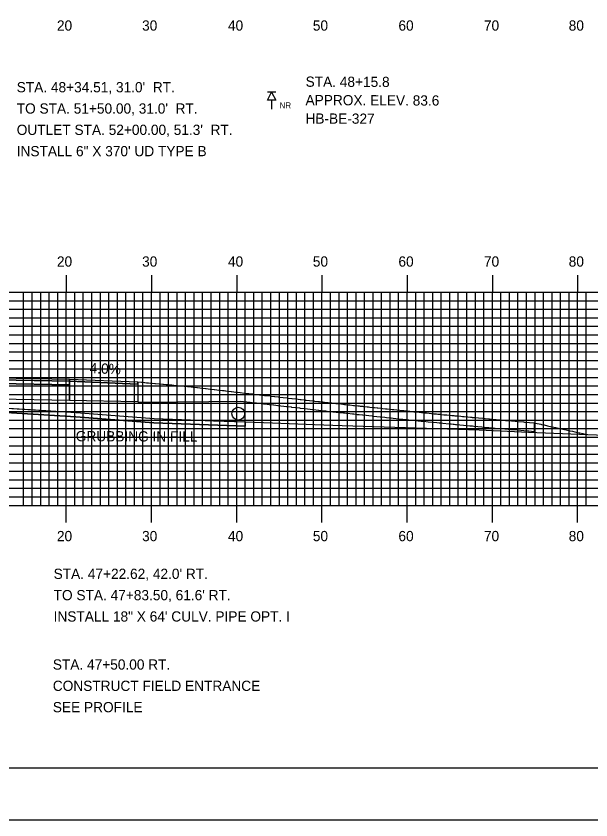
# Model space of a CAD drawing. Extents: x 1754708 to 1755051, y 442591 to 442811.
# Drawn here: x 1754887.6 to 1754955.1, y 442590.5 to 442684.8 of the extents above; entities that cross this region are included whole.
import ezdxf

# ---------------------------------------------------------------- set-up
doc = ezdxf.new("R2010")
doc.units = 0
for name, color, linetype in [('ANNOTATION', 7, 'Continuous'), ('BORDER', 7, 'Continuous'), ('BORING - NO REFUSAL', 7, 'Continuous'), ('D_Drainage_Culvert', 7, 'Continuous'), ('D_Roadway_Centerline', 7, 'Continuous'), ('D_Roadway_Drive_Gravel_RT', 7, 'Continuous'), ('D_Roadway_Drive_SubGrade', 7, 'Continuous'), ('D_Roadway_Edge_Shoulder', 7, 'Continuous'), ('D_Roadway_Edge_TW', 7, 'Continuous'), ('D_Roadway_Pavement', 7, 'Continuous'), ('D_Roadway_SubGrade', 7, 'Continuous'), ('D_Text_Standard', 7, 'Continuous'), ('DIMENSIONS', 7, 'Continuous'), ('GRUBBING IN FILL', 7, 'Continuous'), ('H_V ANNOTATION', 7, 'Continuous'), ('MAJOR', 7, 'Continuous'), ('MINOR', 7, 'Continuous'), ('PLOT BOUNDARY', 7, 'Continuous'), ('S_Roadway_Centerline', 7, 'Continuous')]:
    doc.layers.add(name, color=color, linetype=linetype)

msp = doc.modelspace()

# ---------------------------------------------------------------- linework, layer by layer
at = {"layer": 'ANNOTATION'}
msp.add_lwpolyline([(1754901.917, 442641.915), (1754908.167, 442641.346), (1754913.52, 442640.719)], dxfattribs=at)
at = {"layer": 'BORDER'}
msp.add_lwpolyline([(1754723.917, 442596.665), (1755043.917, 442596.665), (1755043.917, 442806.665), (1754723.917, 442806.665)], close=True, dxfattribs=at)
at = {"layer": 'BORING - NO REFUSAL'}
for p, q in [((1754918.097, 442675.912), (1754917.138, 442675.912)), ((1754917.617, 442674.952), (1754917.617, 442673.893))]:
    msp.add_line(p, q, dxfattribs=at)
msp.add_lwpolyline([(1754917.617, 442675.912), (1754918.097, 442674.952), (1754917.138, 442674.952)], close=True, dxfattribs=at)
at = {"layer": 'D_Drainage_Culvert'}
msp.add_circle((1754913.694, 442638.189), 0.75, dxfattribs=at)
at = {"layer": 'D_Roadway_Centerline'}
for points in [[(1754839.343, 442638.54), (1754843.343, 442639.54), (1754853.517, 442642.083), (1754861.517, 442642.403), (1754873.517, 442642.643), (1754885.517, 442642.403), (1754893.917, 442642.235), (1754901.917, 442641.915)], [(1754901.917, 442641.915), (1754902.417, 442641.87), (1754902.917, 442641.825), (1754903.417, 442641.78), (1754903.917, 442641.735), (1754904.417, 442641.69), (1754904.917, 442641.645), (1754905.417, 442641.6), (1754905.917, 442641.555), (1754906.417, 442641.51), (1754906.917, 442641.465), (1754907.417, 442641.42), (1754907.917, 442641.375), (1754907.917, 442641.375), (1754908.417, 442641.316), (1754908.917, 442641.258), (1754909.417, 442641.199), (1754909.917, 442641.141), (1754910.417, 442641.082), (1754910.472, 442641.076), (1754910.917, 442641.024), (1754910.917, 442641.024), (1754911.417, 442640.965), (1754911.417, 442640.965), (1754911.917, 442640.907), (1754911.917, 442640.907), (1754912.045, 442640.892), (1754912.046, 442640.892), (1754912.417, 442640.848), (1754912.419, 442640.848), (1754912.918, 442640.79), (1754912.921, 442640.789), (1754913.419, 442640.731), (1754913.421, 442640.731), (1754913.62, 442640.708), (1754913.623, 442640.707), (1754913.92, 442640.673), (1754913.926, 442640.672), (1754914.422, 442640.614), (1754914.429, 442640.614), (1754914.925, 442640.556), (1754915.194, 442640.524), (1754915.2, 442640.524), (1754915.423, 442640.498), (1754915.428, 442640.497), (1754915.439, 442640.496), (1754915.932, 442640.439), (1754915.945, 442640.437), (1754916.436, 442640.38), (1754916.773, 442640.341), (1754916.785, 442640.34), (1754916.936, 442640.322), (1754916.942, 442640.322), (1754916.96, 442640.32), (1754917.448, 442640.263), (1754917.47, 442640.261), (1754917.955, 442640.205), (1754917.976, 442640.203), (1754918.38, 442640.156), (1754918.459, 442640.147), (1754918.463, 442640.146), (1754918.492, 442640.143), (1754918.973, 442640.088), (1754919.447, 442640.033), (1754919.483, 442640.029), (1754919.52, 442640.026), (1754919.986, 442639.972), (1754919.995, 442639.971), (1754919.995, 442639.971), (1754920.037, 442639.967), (1754920.509, 442639.912), (1754920.974, 442639.858), (1754921.023, 442639.854), (1754921.074, 442639.849), (1754921.54, 442639.795), (1754921.598, 442639.788), (1754921.605, 442639.788), (1754921.654, 442639.783), (1754922.057, 442639.737), (1754922.511, 442639.684), (1754922.577, 442639.678), (1754922.644, 442639.672), (1754923.098, 442639.62), (1754923.22, 442639.606), (1754923.24, 442639.604), (1754923.565, 442639.567), (1754923.621, 442639.561), (1754924.062, 442639.511), (1754924.146, 442639.503), (1754924.232, 442639.494), (1754924.673, 442639.444), (1754924.854, 442639.423), (1754924.893, 442639.42), (1754925.145, 442639.391), (1754925.202, 442639.386), (1754925.302, 442639.376), (1754925.734, 442639.327), (1754926.155, 442639.279), (1754926.267, 442639.269), (1754926.502, 442639.242), (1754926.567, 442639.236), (1754926.62, 442639.231), (1754926.803, 442639.21), (1754927.213, 442639.164), (1754927.341, 442639.151), (1754927.745, 442639.106), (1754927.882, 442639.093), (1754927.981, 442639.084), (1754928.265, 442639.052), (1754928.382, 442639.039), (1754928.425, 442639.034), (1754928.817, 442638.991), (1754928.971, 442638.976), (1754929.131, 442638.961), (1754929.52, 442638.917), (1754929.664, 442638.904), (1754929.99, 442638.868), (1754930.046, 442638.861), (1754930.072, 442638.859), (1754930.444, 442638.818), (1754930.627, 442638.8), (1754930.991, 442638.76), (1754931.185, 442638.742), (1754931.54, 442638.703), (1754931.744, 442638.684), (1754931.745, 442638.684), (1754931.746, 442638.683), (1754931.959, 442638.664), (1754932.311, 442638.625), (1754932.651, 442638.588), (1754932.879, 442638.566), (1754933.116, 442638.544), (1754933.45, 442638.508), (1754933.497, 442638.503), (1754933.531, 442638.5), (1754933.808, 442638.469), (1754934.026, 442638.449), (1754934.289, 442638.425), (1754934.605, 442638.391), (1754934.909, 442638.358), (1754935.187, 442638.332), (1754935.273, 442638.323), (1754935.355, 442638.316), (1754935.564, 442638.293), (1754935.774, 442638.274), (1754936.08, 442638.246), (1754936.365, 442638.215), (1754936.64, 442638.186), (1754936.961, 442638.157), (1754937.104, 442638.144), (1754937.218, 442638.132), (1754937.367, 442638.116), (1754937.56, 442638.098), (1754937.813, 442638.071), (1754938.164, 442638.04), (1754938.534, 442638.007), (1754938.773, 442637.981), (1754938.994, 442637.962), (1754939.126, 442637.948), (1754939.292, 442637.933), (1754939.387, 442637.923), (1754939.792, 442637.887), (1754940.006, 442637.864), (1754940.21, 442637.843), (1754940.629, 442637.806), (1754940.946, 442637.778), (1754941.082, 442637.764), (1754941.134, 442637.758), (1754941.258, 442637.747), (1754941.436, 442637.729), (1754941.893, 442637.689), (1754942.376, 442637.646), (1754942.533, 442637.63), (1754942.662, 442637.617), (1754943.091, 442637.58), (1754943.16, 442637.574), (1754943.178, 442637.572), (1754943.704, 442637.526), (1754943.83, 442637.513), (1754943.949, 442637.501), (1754944.487, 442637.455), (1754945.06, 442637.406), (1754945.151, 442637.396), (1754945.152, 442637.396), (1754945.158, 442637.396), (1754945.748, 442637.345), (1754945.821, 442637.338), (1754945.891, 442637.331), (1754946.498, 442637.279), (1754946.551, 442637.274), (1754947.182, 442637.221), (1754947.284, 442637.212), (1754947.289, 442637.212), (1754947.859, 442637.164), (1754947.873, 442637.162), (1754948.432, 442637.115), (1754948.571, 442637.085), (1754949.199, 442636.948), (1754949.276, 442636.932), (1754949.459, 442636.892), (1754949.49, 442636.885), (1754949.57, 442636.868), (1754949.989, 442636.776), (1754950.498, 442636.663), (1754950.71, 442636.617), (1754950.971, 442636.56), (1754951.439, 442636.457), (1754951.618, 442636.417), (1754951.766, 442636.384), (1754951.972, 442636.339), (1754952.176, 442636.294), (1754952.618, 442636.196), (1754952.922, 442636.128), (1754953.168, 442636.072), (1754953.677, 442635.96), (1754953.784, 442635.936), (1754954.127, 442635.859), (1754954.392, 442635.8), (1754954.441, 442635.789), (1754954.542, 442635.766), (1754954.631, 442635.746)]]:
    msp.add_lwpolyline(points, dxfattribs=at)
at = {"layer": 'D_Roadway_Drive_Gravel_RT'}
msp.add_line((1754901.917, 442641.915), (1754901.917, 442639.575), dxfattribs=at)
at = {"layer": 'D_Roadway_Drive_SubGrade'}
for p, q in [((1754901.917, 442639.575), (1754902.917, 442639.555)), ((1754902.917, 442639.555), (1754913.917, 442639.666)), ((1754948.432, 442637.115), (1754948.432, 442636.112))]:
    msp.add_line(p, q, dxfattribs=at)
msp.add_lwpolyline([(1754913.917, 442639.666), (1754914.315, 442639.62), (1754914.322, 442639.619), (1754915.087, 442639.53), (1754915.093, 442639.529), (1754915.316, 442639.503), (1754915.332, 442639.502), (1754915.825, 442639.444), (1754915.838, 442639.443), (1754916.666, 442639.347), (1754916.679, 442639.345), (1754916.829, 442639.328), (1754916.854, 442639.325), (1754917.341, 442639.269), (1754917.363, 442639.267), (1754917.849, 442639.21), (1754917.87, 442639.208), (1754918.352, 442639.152), (1754918.386, 442639.149), (1754919.341, 442639.038), (1754919.414, 442639.031), (1754919.889, 442638.976), (1754919.931, 442638.972), (1754920.868, 442638.864), (1754920.969, 442638.854), (1754921.492, 442638.794), (1754921.549, 442638.788), (1754922.406, 442638.69), (1754922.539, 442638.677), (1754923.115, 442638.611), (1754923.135, 442638.609), (1754923.46, 442638.572), (1754923.516, 442638.567), (1754923.958, 442638.516), (1754924.128, 442638.5), (1754924.75, 442638.429), (1754924.789, 442638.425), (1754925.041, 442638.396), (1754925.198, 442638.381), (1754926.051, 442638.285), (1754926.163, 442638.274), (1754926.398, 442638.247), (1754926.516, 442638.236), (1754927.11, 442638.169), (1754927.238, 442638.157), (1754927.642, 442638.111), (1754927.878, 442638.089), (1754928.279, 442638.044), (1754928.322, 442638.04), (1754928.714, 442637.996), (1754929.029, 442637.966), (1754929.418, 442637.923), (1754929.562, 442637.909), (1754929.944, 442637.867), (1754929.97, 442637.864), (1754930.342, 442637.823), (1754930.525, 442637.806), (1754930.889, 442637.765), (1754931.084, 442637.747), (1754931.439, 442637.708), (1754931.644, 442637.689), (1754931.645, 442637.689), (1754931.858, 442637.669), (1754932.55, 442637.593), (1754933.016, 442637.549), (1754933.396, 442637.508), (1754933.431, 442637.505), (1754933.708, 442637.474), (1754934.189, 442637.43), (1754934.809, 442637.363), (1754935.088, 442637.337), (1754935.174, 442637.328), (1754935.256, 442637.321), (1754935.465, 442637.298), (1754935.981, 442637.251), (1754936.541, 442637.191), (1754937.005, 442637.149), (1754937.269, 442637.121), (1754937.462, 442637.103), (1754937.715, 442637.076), (1754938.437, 442637.011), (1754938.676, 442636.986), (1754938.897, 442636.966), (1754939.029, 442636.952), (1754939.195, 442636.937), (1754939.29, 442636.927), (1754939.695, 442636.891), (1754940.114, 442636.847), (1754940.85, 442636.782), (1754941.038, 442636.763), (1754941.163, 442636.752), (1754941.341, 442636.733), (1754942.281, 442636.651), (1754942.568, 442636.621), (1754943.065, 442636.578), (1754943.084, 442636.576), (1754943.61, 442636.53), (1754943.855, 442636.505), (1754944.966, 442636.41), (1754945.059, 442636.4), (1754945.656, 442636.349), (1754945.799, 442636.335), (1754946.406, 442636.283), (1754946.459, 442636.278), (1754947.192, 442636.216), (1754947.198, 442636.216), (1754947.768, 442636.168), (1754947.781, 442636.166), (1754948.432, 442636.112)], dxfattribs=at)
at = {"layer": 'D_Roadway_Edge_Shoulder'}
msp.add_lwpolyline([(1754893.917, 442642.235), (1754901.917, 442641.915), (1754901.917, 442641.665), (1754893.917, 442641.985)], close=True, dxfattribs=at)
at = {"layer": 'D_Roadway_Edge_TW'}
msp.add_lwpolyline([(1754885.517, 442642.403), (1754893.917, 442642.235), (1754893.917, 442641.985), (1754885.517, 442642.153)], close=True, dxfattribs=at)
at = {"layer": 'D_Roadway_Pavement'}
msp.add_lwpolyline([(1754885.517, 442642.153), (1754893.917, 442641.985), (1754893.917, 442641.568), (1754885.517, 442641.736)], close=True, dxfattribs=at)
msp.add_lwpolyline([(1754893.917, 442641.985), (1754893.917, 442641.568)], dxfattribs=at)
msp.add_lwpolyline([(1754893.917, 442641.985), (1754893.917, 442641.568)], dxfattribs=at)
msp.add_lwpolyline([(1754893.917, 442641.985), (1754893.917, 442641.568)], dxfattribs=at)
at = {"layer": 'D_Roadway_SubGrade'}
for points in [[(1754885.517, 442641.736), (1754893.917, 442641.568), (1754893.917, 442639.735), (1754885.517, 442639.903)], [(1754893.917, 442641.568), (1754893.917, 442641.985), (1754901.917, 442641.665), (1754901.917, 442641.915), (1754901.917, 442639.575), (1754893.917, 442639.735)]]:
    msp.add_lwpolyline(points, close=True, dxfattribs=at)
at = {"layer": 'DIMENSIONS'}
msp.add_line((1754901.917, 442641.915), (1754901.917, 442641.915), dxfattribs=at)
at = {"layer": 'GRUBBING IN FILL'}
msp.add_line((1754914.492, 442637.226), (1754914.492, 442636.725), dxfattribs=at)
msp.add_line((1754914.492, 442637.226), (1754914.492, 442636.725), dxfattribs=at)
msp.add_lwpolyline([(1754843.956, 442639.552), (1754848.929, 442638.411), (1754850.713, 442637.977), (1754852.447, 442637.469), (1754852.823, 442637.507), (1754860.439, 442638.236), (1754865.065, 442638.592), (1754876.12, 442638.705), (1754883.943, 442638.499), (1754894.644, 442637.829), (1754903.808, 442637.109), (1754914.492, 442636.725)], dxfattribs=at)
msp.add_lwpolyline([(1754843.956, 442639.552), (1754848.929, 442638.411), (1754850.713, 442637.977), (1754852.447, 442637.469), (1754852.823, 442637.507), (1754860.439, 442638.236), (1754865.065, 442638.592), (1754876.12, 442638.705), (1754883.943, 442638.499), (1754894.644, 442637.829), (1754903.808, 442637.109), (1754914.492, 442636.725)], dxfattribs=at)
msp.add_lwpolyline([(1754873.517, 442639.179), (1754876.124, 442639.205), (1754880.045, 442639.102), (1754883.966, 442638.999), (1754889.322, 442638.663), (1754894.679, 442638.328), (1754899.258, 442637.968), (1754903.837, 442637.608), (1754910.777, 442637.359), (1754914.492, 442637.226), (1754914.492, 442636.725), (1754909.15, 442636.917), (1754903.808, 442637.109), (1754899.226, 442637.469), (1754894.644, 442637.829), (1754883.943, 442638.499), (1754880.032, 442638.602), (1754876.12, 442638.705), (1754873.517, 442638.679)], close=True, dxfattribs=at)
msp.add_lwpolyline([(1754873.517, 442639.179), (1754876.124, 442639.205), (1754880.045, 442639.102), (1754883.966, 442638.999), (1754889.322, 442638.663), (1754894.679, 442638.328), (1754899.258, 442637.968), (1754903.837, 442637.608), (1754910.777, 442637.359), (1754914.492, 442637.226), (1754914.492, 442636.725), (1754909.15, 442636.917), (1754903.808, 442637.109), (1754899.226, 442637.469), (1754894.644, 442637.829), (1754883.943, 442638.499), (1754880.032, 442638.602), (1754876.12, 442638.705), (1754873.517, 442638.679)], close=True, dxfattribs=at)
at = {"layer": 'MAJOR'}
for p, q in [((1754893.517, 442654.44), (1754893.517, 442652.436)), ((1754903.517, 442654.44), (1754903.517, 442652.436)), ((1754913.517, 442654.44), (1754913.517, 442652.436)), ((1754923.517, 442654.44), (1754923.517, 442652.436)), ((1754933.517, 442654.44), (1754933.517, 442652.436)), ((1754943.517, 442654.44), (1754943.517, 442652.436)), ((1754953.517, 442654.44), (1754953.517, 442652.436)), ((1754733.517, 442652.436), (1755013.517, 442652.436)), ((1754733.517, 442652.436), (1755013.517, 442652.436)), ((1754893.517, 442627.436), (1754893.517, 442652.436)), ((1754903.517, 442627.436), (1754903.517, 442652.436)), ((1754913.517, 442627.436), (1754913.517, 442652.436)), ((1754923.517, 442627.436), (1754923.517, 442652.436)), ((1754933.517, 442627.436), (1754933.517, 442652.436)), ((1754943.517, 442627.436), (1754943.517, 442652.436)), ((1754953.517, 442627.436), (1754953.517, 442652.436)), ((1754733.517, 442647.436), (1755013.517, 442647.436)), ((1754733.517, 442642.436), (1755013.517, 442642.436)), ((1754733.517, 442637.436), (1755013.517, 442637.436)), ((1754733.517, 442632.436), (1755013.517, 442632.436)), ((1754733.517, 442627.436), (1755013.517, 442627.436)), ((1754733.517, 442627.436), (1755013.517, 442627.436)), ((1754893.517, 442625.432), (1754893.517, 442627.436)), ((1754903.517, 442625.432), (1754903.517, 442627.436)), ((1754913.517, 442625.432), (1754913.517, 442627.436)), ((1754923.517, 442625.432), (1754923.517, 442627.436)), ((1754933.517, 442625.432), (1754933.517, 442627.436)), ((1754943.517, 442625.432), (1754943.517, 442627.436)), ((1754953.517, 442625.432), (1754953.517, 442627.436))]:
    msp.add_line(p, q, dxfattribs=at)
at = {"layer": 'MINOR'}
for p, q in [((1754888.517, 442627.436), (1754888.517, 442652.436)), ((1754889.517, 442627.436), (1754889.517, 442652.436)), ((1754890.517, 442627.436), (1754890.517, 442652.436)), ((1754891.517, 442627.436), (1754891.517, 442652.436)), ((1754892.517, 442627.436), (1754892.517, 442652.436)), ((1754894.517, 442627.436), (1754894.517, 442652.436)), ((1754895.517, 442627.436), (1754895.517, 442652.436)), ((1754896.517, 442627.436), (1754896.517, 442652.436)), ((1754897.517, 442627.436), (1754897.517, 442652.436)), ((1754898.517, 442627.436), (1754898.517, 442652.436)), ((1754899.517, 442627.436), (1754899.517, 442652.436)), ((1754900.517, 442627.436), (1754900.517, 442652.436)), ((1754901.517, 442627.436), (1754901.517, 442652.436)), ((1754902.517, 442627.436), (1754902.517, 442652.436)), ((1754904.517, 442627.436), (1754904.517, 442652.436)), ((1754905.517, 442627.436), (1754905.517, 442652.436)), ((1754906.517, 442627.436), (1754906.517, 442652.436)), ((1754907.517, 442627.436), (1754907.517, 442652.436)), ((1754908.517, 442627.436), (1754908.517, 442652.436)), ((1754909.517, 442627.436), (1754909.517, 442652.436)), ((1754910.517, 442627.436), (1754910.517, 442652.436)), ((1754911.517, 442627.436), (1754911.517, 442652.436)), ((1754912.517, 442627.436), (1754912.517, 442652.436)), ((1754914.517, 442627.436), (1754914.517, 442652.436)), ((1754915.517, 442627.436), (1754915.517, 442652.436)), ((1754916.517, 442627.436), (1754916.517, 442652.436)), ((1754917.517, 442627.436), (1754917.517, 442652.436)), ((1754918.517, 442627.436), (1754918.517, 442652.436)), ((1754919.517, 442627.436), (1754919.517, 442652.436)), ((1754920.517, 442627.436), (1754920.517, 442652.436)), ((1754921.517, 442627.436), (1754921.517, 442652.436)), ((1754922.517, 442627.436), (1754922.517, 442652.436)), ((1754924.517, 442627.436), (1754924.517, 442652.436)), ((1754925.517, 442627.436), (1754925.517, 442652.436)), ((1754926.517, 442627.436), (1754926.517, 442652.436)), ((1754927.517, 442627.436), (1754927.517, 442652.436)), ((1754928.517, 442627.436), (1754928.517, 442652.436)), ((1754929.517, 442627.436), (1754929.517, 442652.436)), ((1754930.517, 442627.436), (1754930.517, 442652.436)), ((1754931.517, 442627.436), (1754931.517, 442652.436)), ((1754932.517, 442627.436), (1754932.517, 442652.436)), ((1754934.517, 442627.436), (1754934.517, 442652.436)), ((1754935.517, 442627.436), (1754935.517, 442652.436)), ((1754936.517, 442627.436), (1754936.517, 442652.436)), ((1754937.517, 442627.436), (1754937.517, 442652.436)), ((1754938.517, 442627.436), (1754938.517, 442652.436)), ((1754939.517, 442627.436), (1754939.517, 442652.436)), ((1754940.517, 442627.436), (1754940.517, 442652.436)), ((1754941.517, 442627.436), (1754941.517, 442652.436)), ((1754942.517, 442627.436), (1754942.517, 442652.436)), ((1754944.517, 442627.436), (1754944.517, 442652.436)), ((1754945.517, 442627.436), (1754945.517, 442652.436)), ((1754946.517, 442627.436), (1754946.517, 442652.436)), ((1754947.517, 442627.436), (1754947.517, 442652.436)), ((1754948.517, 442627.436), (1754948.517, 442652.436)), ((1754949.517, 442627.436), (1754949.517, 442652.436)), ((1754950.517, 442627.436), (1754950.517, 442652.436)), ((1754951.517, 442627.436), (1754951.517, 442652.436)), ((1754952.517, 442627.436), (1754952.517, 442652.436)), ((1754954.517, 442627.436), (1754954.517, 442652.436)), ((1754733.517, 442651.436), (1755013.517, 442651.436)), ((1754733.517, 442650.436), (1755013.517, 442650.436)), ((1754733.517, 442649.436), (1755013.517, 442649.436)), ((1754733.517, 442648.436), (1755013.517, 442648.436)), ((1754733.517, 442646.436), (1755013.517, 442646.436)), ((1754733.517, 442645.436), (1755013.517, 442645.436)), ((1754733.517, 442644.436), (1755013.517, 442644.436)), ((1754733.517, 442643.436), (1755013.517, 442643.436)), ((1754733.517, 442641.436), (1755013.517, 442641.436)), ((1754733.517, 442640.436), (1755013.517, 442640.436)), ((1754733.517, 442639.436), (1755013.517, 442639.436)), ((1754733.517, 442638.436), (1755013.517, 442638.436)), ((1754733.517, 442636.436), (1755013.517, 442636.436)), ((1754733.517, 442635.436), (1755013.517, 442635.436)), ((1754733.517, 442634.436), (1755013.517, 442634.436)), ((1754733.517, 442633.436), (1755013.517, 442633.436)), ((1754733.517, 442631.436), (1755013.517, 442631.436)), ((1754733.517, 442630.436), (1755013.517, 442630.436)), ((1754733.517, 442629.436), (1755013.517, 442629.436)), ((1754733.517, 442628.436), (1755013.517, 442628.436))]:
    msp.add_line(p, q, dxfattribs=at)
at = {"layer": 'PLOT BOUNDARY'}
msp.add_lwpolyline([(1754707.731, 442590.547), (1755047.731, 442590.547), (1755047.731, 442810.547), (1754707.731, 442810.547)], close=True, dxfattribs=at)
at = {"layer": 'S_Roadway_Centerline'}
msp.add_lwpolyline([(1754812.363, 442642.73), (1754826.567, 442642.536), (1754830.457, 442642.285), (1754836.76, 442641.715), (1754849.044, 442638.898), (1754850.843, 442638.46), (1754852.494, 442637.976), (1754852.774, 442638.004), (1754860.396, 442638.734), (1754865.043, 442639.092), (1754876.124, 442639.205), (1754883.966, 442638.999), (1754894.679, 442638.328), (1754903.837, 442637.608), (1754917.718, 442637.11), (1754922.652, 442636.901), (1754925.871, 442636.792), (1754941.98, 442636.307), (1754947.765, 442636.036), (1754956.702, 442635.659)], dxfattribs=at)

# ---------------------------------------------------------------- texts
at = {"layer": 'ANNOTATION'}
msp.add_text('-4.0%', height=1.2, rotation=357.70939, dxfattribs=at).set_placement((1754895.709, 442642.965))
at = {"layer": 'BORING - NO REFUSAL'}
for s, p in [('STA. 48+15.8', (1754921.598, 442676.53)), ('APPROX. ELEV. 83.6', (1754921.591, 442674.37)), ('HB-BE-327', (1754921.584, 442672.21))]:
    msp.add_text(s, height=1.2, rotation=359.81416, dxfattribs=at).set_placement(p)
msp.add_text('NR', height=0.6998, dxfattribs=at).set_placement((1754918.55, 442673.996))
at = {"layer": 'D_Text_Standard'}
for s, p in [("STA. 48+34.51, 31.0'  RT. ", (1754887.707, 442675.879)), ("TO STA. 51+50.00, 31.0'  RT.", (1754887.707, 442673.379)), ("OUTLET STA. 52+00.00, 51.3'  RT.", (1754887.707, 442670.879)), ('INSTALL 6" X 370\' UD TYPE B', (1754887.707, 442668.379)), ("STA. 47+22.62, 42.0' RT.", (1754892.036, 442618.81)), ("TO STA. 47+83.50, 61.6' RT.", (1754892.036, 442616.31)), ('INSTALL 18" X 64\' CULV. PIPE OPT. I', (1754892.036, 442613.81)), ('STA. 47+50.00 RT.', (1754891.941, 442608.174)), ('CONSTRUCT FIELD ENTRANCE', (1754891.941, 442605.674)), ('SEE PROFILE', (1754891.941, 442603.174))]:
    msp.add_text(s, height=1.2, dxfattribs=at).set_placement(p)
at = {"layer": 'GRUBBING IN FILL'}
msp.add_text('GRUBBING IN FILL', height=1.2, rotation=359.81416, dxfattribs=at).set_placement((1754894.636, 442634.957))
at = {"layer": 'H_V ANNOTATION'}
for s, p in [('20', (1754892.425, 442683.112)), ('30', (1754902.415, 442683.112)), ('40', (1754912.49, 442683.112)), ('50', (1754922.447, 442683.112)), ('60', (1754932.49, 442683.112)), ('70', (1754942.522, 442683.112)), ('80', (1754952.468, 442683.112)), ('20', (1754892.425, 442655.436)), ('30', (1754902.415, 442655.436)), ('40', (1754912.49, 442655.436)), ('50', (1754922.447, 442655.436)), ('60', (1754932.49, 442655.436)), ('70', (1754942.522, 442655.436)), ('80', (1754952.468, 442655.436)), ('20', (1754892.425, 442623.236)), ('30', (1754902.415, 442623.236)), ('40', (1754912.49, 442623.236)), ('50', (1754922.447, 442623.236)), ('60', (1754932.49, 442623.236)), ('70', (1754942.522, 442623.236)), ('80', (1754952.468, 442623.236))]:
    msp.add_text(s, height=1.2, dxfattribs=at).set_placement(p)

doc.saveas('drawing.dxf')
